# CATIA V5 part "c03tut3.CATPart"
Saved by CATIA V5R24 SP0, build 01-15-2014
Part number: c03tut3
Bounding box of the stored display mesh (mm): x 0 to 0, y -100 to 100, z 0 to 90
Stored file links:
  D:\KAVITA\CATIA V5-6R2014 Project_ Kavita\CATIA V5-6R2014_partfiles\Tutorials\c03_catia_v5-6r2014_tut\c03tut3.CATPart
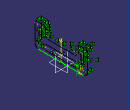
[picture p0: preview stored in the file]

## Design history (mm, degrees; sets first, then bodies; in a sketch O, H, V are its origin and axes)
Body1 (main body)
  Sketch1 on yz-plane, origin (0, 0, 0), H (0, 1, 0), V (0, 0, 1)
    line L1 (0, 0) -> (85, 0)
    line L2 (100, 15) -> (100, 80)
    line L3 (90, 90) -> (70, 90)
    line L4 (60, 80) -> (60, 60)
    line L5 (50, 50) -> (0, 50)
    point P1 (0, 50)
    arc A1 centre (85, 15) radius 15 from (85, 0) to (100, 15) ccw
    point P2 (85, 0)
    point P3 (100, 15)
    arc A2 centre (50, 60) radius 10 from (60, 60) to (50, 50) cw
    point P5 (60, 60)
    point P6 (50, 50)
    arc A3 centre (70, 80) radius 10 from (70, 90) to (60, 80) ccw
    point P8 (70, 90)
    point P9 (60, 80)
    arc A4 centre (90, 80) radius 10 from (100, 80) to (90, 90) ccw
    point P11 (100, 80)
    point P12 (90, 90)
    construction line L6 (80, 70) -> (80, 40)
    line L7 (85, 70) -> (85, 40)
    line L8 (75, 40) -> (75, 70)
    arc A5 centre (80, 40) radius 5 from (85, 40) to (75, 40) cw
    arc A6 centre (80, 70) radius 5 from (75, 70) to (85, 70) cw
    point P16 (85, 70)
    point P17 (85, 40)
    point P18 (75, 40)
    point P19 (75, 70)
    point P20 (0, 0)
    point P21 (0, 50)
    point P22 (-85, 0)
    point P23 (-100, 15)
    point P25 (-60, 60)
    point P26 (-50, 50)
    point P28 (-70, 90)
    point P29 (-60, 80)
    point P31 (-100, 80)
    point P32 (-90, 90)
    construction line L9 (-80, 70) -> (-80, 40)
    point P36 (-85, 70)
    point P37 (-85, 40)
    point P38 (-75, 40)
    point P39 (-75, 70)
    line L10 (0, 0) -> (-85, 0)
    line L11 (-100, 15) -> (-100, 80)
    line L12 (-90, 90) -> (-70, 90)
    line L13 (-60, 80) -> (-60, 60)
    line L14 (-50, 50) -> (0, 50)
    arc A7 centre (-85, 15) radius 15 from (-85, 0) to (-100, 15) cw
    arc A8 centre (-50, 60) radius 10 from (-60, 60) to (-50, 50) ccw
    arc A9 centre (-70, 80) radius 10 from (-70, 90) to (-60, 80) cw
    arc A10 centre (-90, 80) radius 10 from (-100, 80) to (-90, 90) cw
    line L15 (-85, 70) -> (-85, 40)
    line L16 (-75, 40) -> (-75, 70)
    arc A11 centre (-80, 40) radius 5 from (-85, 40) to (-75, 40) ccw
    arc A12 centre (-80, 70) radius 5 from (-75, 70) to (-85, 70) ccw
    construction line L17 (60, 20) -> (-60, 20)
    point P40 (60, 20)
    line L18 (60, 10) -> (-60, 10)
    line L19 (-60, 30) -> (60, 30)
    arc A13 centre (-60, 20) radius 10 from (-60, 10) to (-60, 30) cw
    arc A14 centre (60, 20) radius 10 from (60, 30) to (60, 10) cw
    radius A1 = 15
    radius A2 = 10
    radius A3 = 10
    radius A4 = 10
    distance L6 L7 = 5
    distance L17 L18 = 10
    horizontal: L1 H, L3 H, L5 H, L17 H
    vertical: L2 V, L4 V
    coincidence: P1 V, P40 L4
    tangency: A1 L1, A1 L2, A2 L4, A2 L5, A3 L3, A3 L4, A4 L2, A4 L3, L6 A3, A5 L7, A6 L7, A5 L8, A6 L8, A13 L18, A14 L18, A13 L19, A14 L19
    symmetry: O P20 V, P1 P21 V, P2 P22 V, P3 P23 V, P5 P25 V, P6 P26 V, P8 P28 V, P9 P29 V, P11 P31 V, P12 P32 V, L6 L9 V, P16 P36 V, P17 P37 V, P18 P38 V, P19 P39 V, L1 L10 V, L2 L11 V, L3 L12 V, L4 L13 V, L5 L14 V, A1 A7 V, A2 A8 V, A3 A9 V, A4 A10 V, L7 L15 V, L8 L16 V, A5 A11 V, A6 A12 V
